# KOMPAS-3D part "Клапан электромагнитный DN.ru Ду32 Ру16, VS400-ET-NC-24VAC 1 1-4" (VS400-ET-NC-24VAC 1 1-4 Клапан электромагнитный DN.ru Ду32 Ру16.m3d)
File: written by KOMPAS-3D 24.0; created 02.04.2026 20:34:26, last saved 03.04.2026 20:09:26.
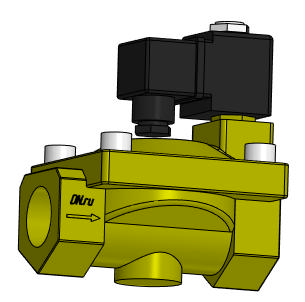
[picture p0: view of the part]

Document properties: Автор: artio; Полное имя файла: C:\Users\artio\OneDrive\Рабочий стол\Клапан электромагнитный DN.ru\VS400-ET-NC\VS400-ET-NC-24VAC 1 1-4 Клапан электромагнитный DN.ru Ду32 Ру16.m3d

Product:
- Body: Тело 1  | qty 1
    Масса: 4.144257
- Part/product: Клапан электромагнитный DN.ru Ду32 Ру16  | designation VS400-ET-NC-24VAC 1 1-4
    Масса: 2.569
    Раздел спецификации: Прочие изделия
    Примечание: D130-05490
    additional columns: ef56311e-7521-43dc-8291-0e6108b3d81d; VS400-ET-NC-220VAC 1 1-4; artio; c; Шероховатость не задана; Да

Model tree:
1. Операция без истории:1

Expressions: VS400-ET-NC-24VAC 1 1-4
